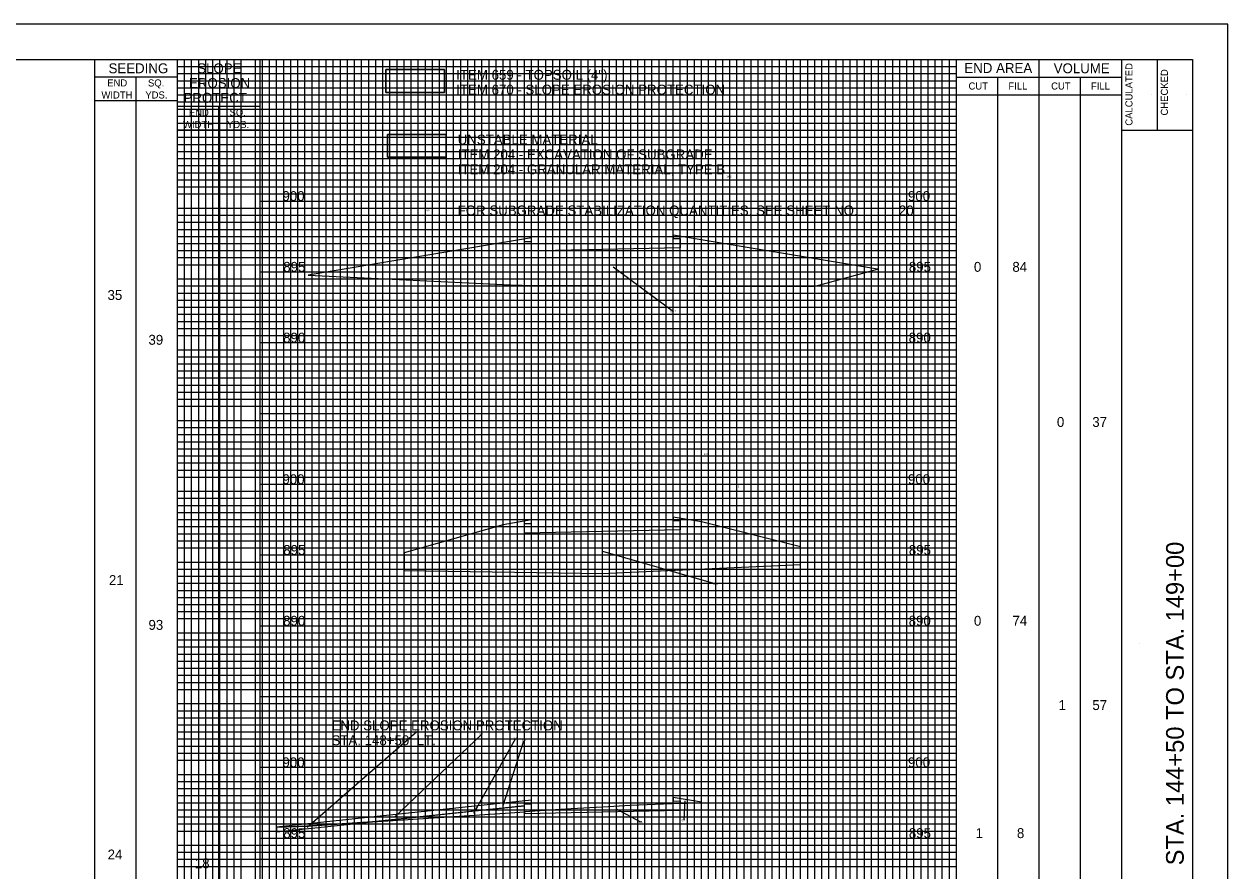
# Model space of a CAD drawing. Extents: x -73 to 160, y -2 to 1877.
# Drawn here: x 75 to 160, y 47.7 to 107.5 of the extents above; entities that cross this region are included whole.
import ezdxf

# ---------------------------------------------------------------- set-up
doc = ezdxf.new("R2010")
doc.units = 0
for name, color, linetype in [('DR_P_Flood_Boundary', 7, 'Continuous'), ('GK_Cells', 7, 'Continuous'), ('PV_P_Drive', 7, 'Continuous'), ('PV_P_EOP', 7, 'Continuous'), ('RD_X_Fence', 7, 'Continuous'), ('TX_X_5', 7, 'Continuous'), ('UT_P_Water_Cells', 7, 'Continuous'), ('XS_P_Pavt_Surface', 7, 'Continuous'), ('XS_P_Special_Benching', 7, 'Continuous'), ('XS_X_Ground_Line', 7, 'Continuous')]:
    doc.layers.add(name, color=color, linetype=linetype)

msp = doc.modelspace()

# ---------------------------------------------------------------- linework, layer by layer
at = {"layer": 'DR_P_Flood_Boundary'}
for p, q in [((95.832, 0), (95.832, 105)), ((100.832, 0), (100.832, 105)), ((105.832, 0), (105.832, 105)), ((110.832, 0), (110.832, 105)), ((115.832, 0), (115.832, 105)), ((120.832, 0), (120.832, 105)), ((125.832, 0), (125.832, 105)), ((130.832, 0), (130.832, 105)), ((135.832, 0), (135.832, 105)), ((85.832, 100), (140.832, 100)), ((91.665, 95), (140.832, 95)), ((91.665, 90), (140.832, 90)), ((91.665, 85), (140.832, 85)), ((91.665, 80), (140.832, 80)), ((91.665, 75), (140.832, 75)), ((91.665, 70), (140.832, 70)), ((91.665, 65), (140.832, 65)), ((91.665, 60), (140.832, 60)), ((91.665, 55), (140.832, 55)), ((91.665, 50), (140.832, 50))]:
    msp.add_line(p, q, dxfattribs=at)
at = {"layer": 'GK_Cells'}
for p, q in [((152.5, 0), (152.5, 105)), ((155, 105), (155, 100)), ((152.5, 100), (157.5, 100))]:
    msp.add_line(p, q, dxfattribs=at)
msp.add_lwpolyline([(0, 105), (157.5, 105), (157.5, 0), (0, 0)], close=True, dxfattribs=at)
at = {"layer": 'PV_P_Drive'}
msp.add_lwpolyline([(100.547, 104.281), (104.687, 104.281), (104.687, 102.666), (100.547, 102.666)], close=True, dxfattribs=at)
msp.add_lwpolyline([(100.547, 102.666), (104.687, 102.666), (104.687, 104.281), (100.547, 104.281), (100.547, 102.666)], dxfattribs=at)
at = {"layer": 'PV_P_EOP'}
msp.add_lwpolyline([(100.65, 99.704), (104.791, 99.704), (104.791, 98.089), (100.65, 98.089)], close=True, dxfattribs=at)
msp.add_lwpolyline([(100.65, 98.089), (104.791, 98.089), (104.791, 99.704), (100.65, 99.704), (100.65, 98.089)], dxfattribs=at)
at = {"layer": 'RD_X_Fence'}
for p, q in [((110.832, 92.397), (95.052, 89.766)), ((110.332, 92.137), (110.832, 92.147)), ((110.332, 91.47), (110.332, 92.137)), ((135.269, 90.19), (120.832, 92.597)), ((120.832, 92.347), (121.332, 92.357)), ((121.332, 92.357), (121.332, 91.69)), ((121.332, 91.69), (110.332, 91.47)), ((116.598, 90.342), (120.857, 87.205)), ((110.832, 72.47), (108.832, 72.137)), ((122.832, 72.337), (120.832, 72.67)), ((120.832, 72.42), (121.332, 72.43)), ((121.332, 72.43), (121.332, 71.763)), ((129.832, 70.58), (122.832, 72.337)), ((108.832, 72.137), (101.832, 70.15)), ((110.332, 72.21), (110.832, 72.22)), ((110.332, 71.543), (110.332, 72.21)), ((121.332, 71.763), (110.332, 71.543)), ((129.832, 69.33), (129.832, 70.58)), ((101.832, 70.15), (101.832, 68.9)), ((115.833, 70.279), (123.838, 67.95)), ((94.986, 50.769), (102.736, 57.537)), ((101.185, 51.504), (107.302, 57.329)), ((106.757, 51.767), (109.715, 57.062)), ((108.816, 52.294), (110.288, 56.876)), ((122.832, 52.535), (120.832, 52.868)), ((107.037, 52.268), (92.833, 50.771)), ((110.332, 52.285), (99.605, 51.155)), ((99.605, 51.155), (106.841, 51.917)), ((106.841, 51.917), (110.332, 52.285)), ((106.841, 51.917), (107.037, 52.268)), ((107.037, 52.268), (106.841, 51.917)), ((110.832, 52.668), (107.037, 52.268)), ((110.332, 52.408), (110.832, 52.418)), ((110.332, 52.285), (110.332, 52.408)), ((110.332, 51.86), (110.332, 52.285)), ((110.332, 51.741), (121.332, 51.961)), ((110.332, 51.86), (110.332, 51.741)), ((110.832, 52.564), (110.832, 52.668)), ((110.832, 52.418), (110.832, 52.564)), ((116.845, 52.054), (118.535, 51.14)), ((120.832, 52.618), (121.332, 52.628)), ((121.332, 52.628), (121.332, 52.446)), ((121.332, 52.446), (122.834, 52.509)), ((121.332, 51.961), (121.332, 52.446)), ((121.65, 52.621), (121.583, 51.263)), ((92.833, 50.441), (99.605, 51.155)), ((92.833, 50.771), (92.833, 50.441))]:
    msp.add_line(p, q, dxfattribs=at)
for points in [[(110.832, 92.147), (110.832, 92.292), (110.832, 92.397)], [(120.832, 92.597), (120.832, 92.492), (120.832, 92.347)], [(95.052, 89.766), (109.863, 89.063), (110.165, 89.047), (115.832, 89.023), (122.61, 88.994), (130.865, 88.976), (135.269, 90.19)], [(110.832, 72.22), (110.832, 72.366), (110.832, 72.47)], [(120.832, 72.67), (120.832, 72.566), (120.832, 72.42)], [(101.832, 68.9), (115.829, 68.692), (120.451, 68.903), (129.832, 69.33)], [(120.832, 52.868), (120.832, 52.764), (120.832, 52.618)], [(99.605, 51.155), (109.328, 51.794), (110.332, 51.86)], [(121.332, 52.446), (117.829, 52.299), (115.833, 52.193), (113.619, 52.076), (110.332, 51.86)], [(122.834, 52.509), (122.832, 52.535)], [(92.833, 50.771), (94.971, 50.85), (99.605, 51.155)], [(99.605, 51.155), (94.971, 50.85), (92.833, 50.771)]]:
    msp.add_lwpolyline(points, dxfattribs=at)
at = {"layer": 'TX_X_5'}
msp.add_lwpolyline([(-10, -2.5), (160, -2.5), (160, 107.5), (-10, 107.5)], close=True, dxfattribs=at)
at = {"layer": 'UT_P_Water_Cells'}
for p, q in [((86.332, 0), (86.332, 105)), ((86.832, 0), (86.832, 105)), ((87.332, 0), (87.332, 105)), ((87.832, 0), (87.832, 105)), ((88.332, 0), (88.332, 105)), ((88.832, 0), (88.832, 105)), ((89.332, 0), (89.332, 105)), ((89.832, 0), (89.832, 105)), ((90.332, 0), (90.332, 105)), ((91.332, 0), (91.332, 105)), ((91.832, 0), (91.832, 105)), ((92.332, 0), (92.332, 105)), ((92.832, 0), (92.832, 105)), ((93.332, 0), (93.332, 105)), ((93.832, 0), (93.832, 105)), ((94.332, 0), (94.332, 105)), ((94.832, 0), (94.832, 105)), ((95.332, 0), (95.332, 105)), ((96.332, 0), (96.332, 105)), ((96.832, 0), (96.832, 105)), ((97.332, 0), (97.332, 105)), ((97.832, 0), (97.832, 105)), ((98.332, 0), (98.332, 105)), ((98.832, 0), (98.832, 105)), ((99.332, 0), (99.332, 105)), ((99.832, 0), (99.832, 105)), ((100.332, 0), (100.332, 105)), ((101.332, 0), (101.332, 105)), ((101.832, 0), (101.832, 105)), ((102.332, 0), (102.332, 105)), ((102.832, 0), (102.832, 105)), ((103.332, 0), (103.332, 105)), ((103.832, 0), (103.832, 105)), ((104.332, 0), (104.332, 105)), ((104.832, 0), (104.832, 105)), ((105.332, 0), (105.332, 105)), ((106.332, 0), (106.332, 105)), ((106.832, 0), (106.832, 105)), ((107.332, 0), (107.332, 105)), ((107.832, 0), (107.832, 105)), ((108.332, 0), (108.332, 105)), ((108.832, 0), (108.832, 105)), ((109.332, 0), (109.332, 105)), ((109.832, 0), (109.832, 105)), ((110.332, 0), (110.332, 105)), ((111.332, 0), (111.332, 105)), ((111.832, 0), (111.832, 105)), ((112.332, 0), (112.332, 105)), ((112.832, 0), (112.832, 105)), ((113.332, 0), (113.332, 105)), ((113.832, 0), (113.832, 105)), ((114.332, 0), (114.332, 105)), ((114.832, 0), (114.832, 105)), ((115.332, 0), (115.332, 105)), ((116.332, 0), (116.332, 105)), ((116.832, 0), (116.832, 105)), ((117.332, 0), (117.332, 105)), ((117.832, 0), (117.832, 105)), ((118.332, 0), (118.332, 105)), ((118.832, 0), (118.832, 105)), ((119.332, 0), (119.332, 105)), ((119.832, 0), (119.832, 105)), ((120.332, 0), (120.332, 105)), ((121.332, 0), (121.332, 105)), ((121.832, 0), (121.832, 105)), ((122.332, 0), (122.332, 105)), ((122.832, 0), (122.832, 105)), ((123.332, 0), (123.332, 105)), ((123.832, 0), (123.832, 105)), ((124.332, 0), (124.332, 105)), ((124.832, 0), (124.832, 105)), ((125.332, 0), (125.332, 105)), ((126.332, 0), (126.332, 105)), ((126.832, 0), (126.832, 105)), ((127.332, 0), (127.332, 105)), ((127.832, 0), (127.832, 105)), ((128.332, 0), (128.332, 105)), ((128.832, 0), (128.832, 105)), ((129.332, 0), (129.332, 105)), ((129.832, 0), (129.832, 105)), ((130.332, 0), (130.332, 105)), ((131.332, 0), (131.332, 105)), ((131.832, 0), (131.832, 105)), ((132.332, 0), (132.332, 105)), ((132.832, 0), (132.832, 105)), ((133.332, 0), (133.332, 105)), ((133.832, 0), (133.832, 105)), ((134.332, 0), (134.332, 105)), ((134.832, 0), (134.832, 105)), ((135.332, 0), (135.332, 105)), ((136.332, 0), (136.332, 105)), ((136.832, 0), (136.832, 105)), ((137.332, 0), (137.332, 105)), ((137.832, 0), (137.832, 105)), ((138.332, 0), (138.332, 105)), ((138.832, 0), (138.832, 105)), ((139.332, 0), (139.332, 105)), ((139.832, 0), (139.832, 105)), ((140.332, 0), (140.332, 105)), ((85.832, 104.5), (140.832, 104.5)), ((85.832, 104), (140.832, 104)), ((85.832, 103.5), (140.832, 103.5)), ((85.832, 103), (140.832, 103)), ((85.832, 102.5), (140.832, 102.5)), ((85.832, 102), (140.832, 102)), ((85.832, 101.5), (140.832, 101.5)), ((85.832, 101), (140.832, 101)), ((85.832, 100.5), (140.832, 100.5)), ((85.832, 99.5), (140.832, 99.5)), ((85.832, 99), (140.832, 99)), ((85.832, 98.5), (140.832, 98.5)), ((85.832, 98), (140.832, 98)), ((85.832, 97.5), (140.832, 97.5)), ((85.832, 97), (140.832, 97)), ((85.832, 96.5), (140.832, 96.5)), ((85.832, 96), (140.832, 96)), ((85.832, 95.5), (140.832, 95.5)), ((85.832, 94.5), (140.832, 94.5)), ((85.832, 94), (140.832, 94)), ((85.832, 93.5), (140.832, 93.5)), ((85.832, 93), (140.832, 93)), ((85.832, 92.5), (140.832, 92.5)), ((85.832, 92), (140.832, 92)), ((85.832, 91.5), (140.832, 91.5)), ((85.832, 91), (140.832, 91)), ((85.832, 90.5), (140.832, 90.5)), ((85.832, 89.5), (140.832, 89.5)), ((85.832, 89), (140.832, 89)), ((85.832, 88.5), (140.832, 88.5)), ((85.832, 88), (140.832, 88)), ((85.832, 87.5), (140.832, 87.5)), ((85.832, 87), (140.832, 87)), ((85.832, 86.5), (140.832, 86.5)), ((85.832, 86), (140.832, 86)), ((85.832, 85.5), (140.832, 85.5)), ((85.832, 84.5), (140.832, 84.5)), ((85.832, 84), (140.832, 84)), ((85.832, 83.5), (140.832, 83.5)), ((85.832, 83), (140.832, 83)), ((85.832, 82.5), (140.832, 82.5)), ((85.832, 82), (140.832, 82)), ((85.832, 81.5), (140.832, 81.5)), ((85.832, 81), (140.832, 81)), ((85.832, 80.5), (140.832, 80.5)), ((85.832, 79.5), (140.832, 79.5)), ((85.832, 79), (140.832, 79)), ((85.832, 78.5), (140.832, 78.5)), ((85.832, 78), (140.832, 78)), ((85.832, 77.5), (140.832, 77.5)), ((85.832, 77), (140.832, 77)), ((85.832, 76.5), (140.832, 76.5)), ((85.832, 76), (140.832, 76)), ((85.832, 75.5), (140.832, 75.5)), ((85.832, 74.5), (140.832, 74.5)), ((85.832, 74), (140.832, 74)), ((85.832, 73.5), (140.832, 73.5)), ((85.832, 73), (140.832, 73)), ((85.832, 72.5), (140.832, 72.5)), ((85.832, 72), (140.832, 72)), ((85.832, 71.5), (140.832, 71.5)), ((85.832, 71), (140.832, 71)), ((85.832, 70.5), (140.832, 70.5)), ((85.832, 69.5), (140.832, 69.5)), ((85.832, 69), (140.832, 69)), ((85.832, 68.5), (140.832, 68.5)), ((85.832, 68), (140.832, 68)), ((85.832, 67.5), (140.832, 67.5)), ((85.832, 67), (140.832, 67)), ((85.832, 66.5), (140.832, 66.5)), ((85.832, 66), (140.832, 66)), ((85.832, 65.5), (140.832, 65.5)), ((85.832, 64.5), (140.832, 64.5)), ((85.832, 64), (140.832, 64)), ((85.832, 63.5), (140.832, 63.5)), ((85.832, 63), (140.832, 63)), ((85.832, 62.5), (140.832, 62.5)), ((85.832, 62), (140.832, 62)), ((85.832, 61.5), (140.832, 61.5)), ((85.832, 61), (140.832, 61)), ((85.832, 60.5), (140.832, 60.5)), ((85.832, 59.5), (140.832, 59.5)), ((85.832, 59), (140.832, 59)), ((85.832, 58.5), (140.832, 58.5)), ((85.832, 58), (140.832, 58)), ((85.832, 57.5), (140.832, 57.5)), ((85.832, 57), (140.832, 57)), ((85.832, 56.5), (140.832, 56.5)), ((85.832, 56), (140.832, 56)), ((85.832, 55.5), (140.832, 55.5)), ((85.832, 54.5), (140.832, 54.5)), ((85.832, 54), (140.832, 54)), ((85.832, 53.5), (140.832, 53.5)), ((85.832, 53), (140.832, 53)), ((85.832, 52.5), (140.832, 52.5)), ((85.832, 52), (140.832, 52)), ((85.832, 51.5), (140.832, 51.5)), ((85.832, 51), (140.832, 51)), ((85.832, 50.5), (140.832, 50.5)), ((85.832, 49.5), (140.832, 49.5)), ((85.832, 49), (140.832, 49)), ((85.832, 48.5), (140.832, 48.5)), ((85.832, 48), (140.832, 48))]:
    msp.add_line(p, q, dxfattribs=at)
at = {"layer": 'XS_X_Ground_Line'}
for p, q in [((80, 0), (80, 105)), ((85.832, 0), (85.832, 105)), ((85.832, 0), (85.832, 105)), ((91.665, 0), (91.665, 105)), ((140.832, 0), (140.832, 105)), ((146.667, 0), (146.667, 105)), ((85.832, 103.75), (80, 103.75)), ((82.916, 0), (82.916, 103.75)), ((140.832, 103.75), (152.5, 103.75)), ((143.75, 0), (143.75, 103.75)), ((149.583, 0), (149.583, 103.75)), ((85.832, 102.083), (80, 102.083)), ((140.832, 102.5), (152.5, 102.5)), ((154.6, 102.518), (154.6, 102.518)), ((157.1, 102.518), (157.1, 102.518)), ((91.665, 101.667), (85.832, 101.667)), ((88.749, 0), (88.749, 101.667)), ((91.665, 100), (85.832, 100)), ((153.75, 63.75), (153.75, 63.75)), ((156.258, 63.75), (156.258, 63.75))]:
    msp.add_line(p, q, dxfattribs=at)

# ---------------------------------------------------------------- texts
at = {"layer": 'RD_X_Fence'}
for s, p in [('14.6', (124.582, 96.658)), ('16.0', (103.289, 94.284)), ('83.7', (120.649, 87.135)), ('2.0', (122.995, 77.065)), ('7.2', (125.229, 74.786)), ('7.3', (103.256, 72.364)), ('74.4', (123.632, 67.88)), ('1.0', (102.602, 57.467)), ('3.7', (107.138, 57.259)), ('2.3', (109.556, 56.992)), ('1.2', (110.158, 56.806)), ('3.6', (118.384, 51.07)), ('0.4', (121.431, 51.193))]:
    msp.add_text(s, height=0.14, dxfattribs=at).set_placement(p)
at = {"layer": 'XS_P_Pavt_Surface'}
for s, p in [('900', (93.243, 95)), ('900', (137.41, 95)), ('895', (93.303, 90)), ('895', (137.471, 90)), ('0', (142.067, 90)), ('84', (144.782, 90)), ('35', (80.893, 88.011)), ('39', (83.781, 84.848)), ('890', (93.292, 85)), ('890', (137.46, 85)), ('0', (147.925, 79.044)), ('37', (150.424, 79.044)), ('900', (93.243, 75)), ('900', (137.41, 75)), ('895', (93.303, 70)), ('895', (137.471, 70)), ('21', (80.992, 67.873)), ('890', (93.292, 65)), ('890', (137.46, 65)), ('0', (142.067, 65)), ('74', (144.787, 65)), ('93', (83.784, 64.71)), ('1', (148.04, 59.044)), ('57', (150.43, 59.044)), ('END SLOPE EROSION PROTECTION', (96.708, 57.61)), ('STA. 148+50, LT.', (96.708, 56.56)), ('900', (93.243, 55)), ('900', (137.41, 55)), ('895', (93.303, 50)), ('895', (137.471, 50)), ('1', (142.182, 50)), ('8', (145.102, 50)), ('24', (80.899, 48.489)), ('18', (87.054, 47.87))]:
    msp.add_text(s, height=0.7, dxfattribs=at).set_placement(p)
at = {"layer": 'XS_P_Special_Benching'}
for s, p in [('ITEM 659 - TOPSOIL (4")', (105.515, 103.567)), ('ITEM 670 - SLOPE EROSION PROTECTION', (105.515, 102.517)), ('UNSTABLE MATERIAL', (105.618, 98.99)), ('ITEM 204 - EXCAVATION OF SUBGRADE', (105.618, 97.94)), ('ITEM 204 - GRANULAR MATERIAL, TYPE B', (105.618, 96.89)), ('FOR SUBGRADE STABILIZATION QUANTITIES, SEE SHEET NO.', (105.618, 93.983)), ('20', (136.768, 93.983))]:
    msp.add_text(s, height=0.7, dxfattribs=at).set_placement(p)
at = {"layer": 'XS_X_Ground_Line'}
for s, height, p in [('SEEDING', 0.7, (80.964, 104.025)), ('SLOPE', 0.7, (87.228, 104.025)), ('END AREA', 0.7, (141.394, 104.047)), ('VOLUME', 0.7, (147.698, 104.025)), ('END', 0.5, (80.87, 103.092)), ('SQ.', 0.5, (83.748, 103.092)), ('EROSION', 0.7, (86.649, 102.983)), ('CUT', 0.5, (141.683, 102.875)), ('FILL', 0.5, (144.502, 102.875)), ('CUT', 0.5, (147.517, 102.875)), ('FILL', 0.5, (150.335, 102.875)), ('WIDTH', 0.5, (80.462, 102.242)), ('YDS.', 0.5, (83.563, 102.242)), ('PROTECT.', 0.7, (86.26, 101.942)), ('END', 0.5, (86.631, 101.008)), ('SQ.', 0.5, (89.51, 101.008)), ('WIDTH', 0.5, (86.224, 100.158)), ('YDS.', 0.5, (89.325, 100.158))]:
    msp.add_text(s, height=height, dxfattribs=at).set_placement(p)
for s, height, p in [('CALCULATED', 0.5, (153.262, 100.323)), ('CHECKED', 0.5, (155.762, 101.04)), ('STA. 144+50 TO STA. 149+00', 1.25, (156.883, 48.076))]:
    msp.add_text(s, height=height, rotation=90, dxfattribs=at).set_placement(p)

doc.saveas('drawing.dxf')
